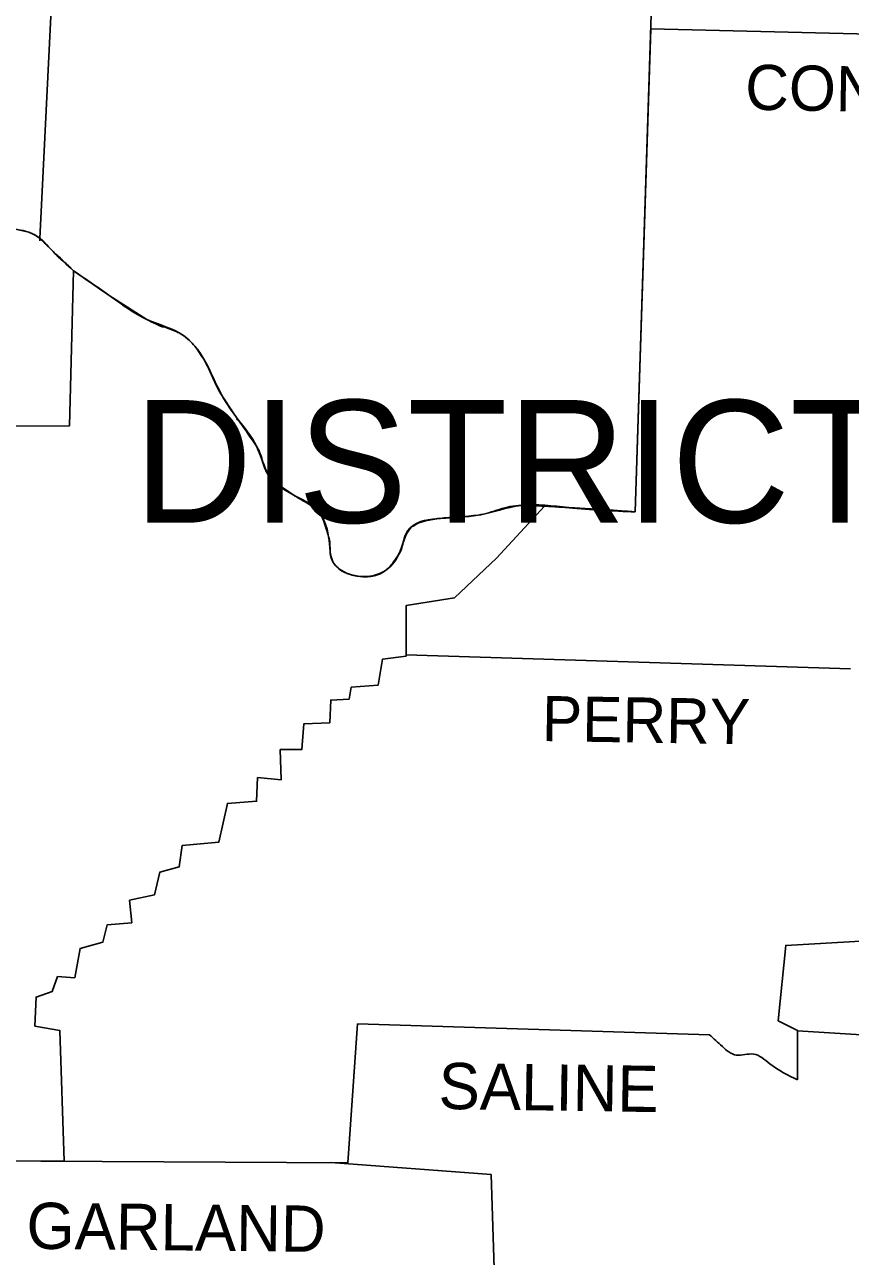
# Model space of a CAD drawing. Extents: x -13171 to 18763, y -8840 to 11152.
# Drawn here: x 12315 to 13066, y 7625 to 8746 of the extents above; entities that cross this region are included whole.
import ezdxf

# ---------------------------------------------------------------- set-up
doc = ezdxf.new("R2010")
doc.units = 0
for name, color, linetype in [('Level 1', 7, 'Continuous'), ('Level 2', 7, 'Continuous'), ('Level 3', 7, 'Continuous'), ('Level 48', 7, 'Continuous')]:
    doc.layers.add(name, color=color, linetype=linetype)

msp = doc.modelspace()

# ---------------------------------------------------------------- linework, layer by layer
at = {"layer": 'Level 1'}
msp.add_line((12329.114520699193, 8551.202475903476), (12329.114520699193, 8548.948933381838), dxfattribs=at)
for points in [[(12499.696812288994, 9145.12204334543), (12498.69559730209, 8957.894828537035), (12431.185526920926, 8956.91642185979), (12425.31508598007, 8762.213465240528), (12339.215285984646, 8759.278244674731), (12329.114520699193, 8551.202475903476)], [(12938.043358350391, 9141.567882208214), (12936.043444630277, 8881.5790968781), (12889.079917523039, 8877.665469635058), (12870.490187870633, 8302.362261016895)], [(12884.687301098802, 8741.72555171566), (13334.255019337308, 8730.904446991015), (13328.384578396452, 8489.23796307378)], [(12359.761829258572, 8521.525388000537), (12355.84820201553, 8380.634806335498), (12132.771447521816, 8379.656399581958)], [(12787.889158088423, 8307.538671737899), (12744.275708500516, 8260.290767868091), (12706.11784251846, 8224.089715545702), (12662.089535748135, 8217.240867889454), (12662.089535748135, 8171.255747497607), (12640.564585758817, 8168.320526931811), (12636.650958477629, 8144.838763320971), (12612.190788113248, 8142.881949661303), (12610.23397445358, 8132.119474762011), (12593.60105861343, 8131.141068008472), (12592.622651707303, 8110.594524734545), (12569.140888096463, 8109.616117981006), (12567.184074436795, 8086.134354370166), (12547.615938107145, 8086.134354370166), (12548.594344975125, 8058.73896343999), (12527.069394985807, 8060.695777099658), (12526.090988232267, 8039.170827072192), (12499.67400405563, 8037.214013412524), (12491.8467495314, 8001.991368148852), (12458.580917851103, 7999.056147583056), (12455.645697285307, 7979.488011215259), (12438.034374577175, 7974.595977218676), (12433.142340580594, 7954.0494339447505), (12410.638983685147, 7949.157399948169), (12412.595797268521, 7928.610856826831), (12390.092440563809, 7926.654043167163), (12386.178813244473, 7910.999534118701), (12365.632270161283, 7905.129093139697), (12360.740235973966, 7878.712108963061), (12345.085726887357, 7879.690515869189), (12340.193692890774, 7865.992820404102), (12325.517590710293, 7861.100786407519), (12324.539183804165, 7834.683802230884), (12347.042540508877, 7830.7701749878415), (12351.147833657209, 7711.716675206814)], [(13066.17155143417, 8159.514865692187), (12662.089535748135, 8172.265026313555)], [(13327.406171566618, 7976.552790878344), (13256.960880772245, 7984.380045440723), (13259.896101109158, 7957.963061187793), (13131.724808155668, 7953.07102719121), (13127.811180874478, 7914.913161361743), (13007.46714229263, 7908.064313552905), (13000.61829463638, 7839.575836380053), (13018.229617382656, 7830.7701749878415), (13018.229617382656, 7785.763461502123)], [(12938.000258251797, 7826.856547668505), (12618.061229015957, 7836.640615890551), (12609.255567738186, 7710.426136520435), (12217.892840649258, 7712.382950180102), (12215.936027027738, 7670.3114568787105)], [(13018.229617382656, 7830.219821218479), (13134.660028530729, 7822.942920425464), (13130.74640124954, 7700.642068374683), (13258.917694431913, 7695.7500342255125), (13260.874508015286, 7589.103690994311), (13321.53573062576, 7584.211657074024), (13321.53573062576, 7565.621927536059), (13378.283326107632, 7561.708300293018), (13380.240139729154, 7493.219822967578), (13509.389839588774, 7493.219822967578), (13513.303466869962, 7425.709752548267), (13632.669098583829, 7419.83931172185), (13631.689211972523, 7292.454043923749)], [(12593.638354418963, 7710.504222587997), (12739.383674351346, 7699.663661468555), (12743.297301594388, 7576.384402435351), (12726.664385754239, 7570.5139616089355), (12724.707572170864, 7504.960704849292), (12852.878865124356, 7496.155043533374), (12852.878865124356, 7442.34266857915), (12938.000258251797, 7437.45063442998), (12938.978665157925, 7383.638259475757), (12959.525208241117, 7380.703038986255), (12958.480338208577, 7303.382645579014)]]:
    msp.add_lwpolyline(points, dxfattribs=at)
for points in [[(11843.163029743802, 8639.912612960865), (11875.45045467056, 8650.67508793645), (11898.932218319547, 8652.631901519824), (11922.413981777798, 8648.718274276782), (11946.874152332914, 8638.934206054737), (11973.291136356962, 8640.891019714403), (11992.85927272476, 8647.739867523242), (12012.427409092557, 8660.459156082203), (12033.952359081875, 8664.372783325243), (12054.498902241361, 8660.459156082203), (12076.023852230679, 8654.588715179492), (12099.50561584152, 8661.43756298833), (12113.203311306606, 8674.15685154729), (12136.685074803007, 8678.070478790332), (12157.231618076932, 8678.070478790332), (12171.907720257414, 8661.43756298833), (12174.84294082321, 8643.826240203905), (12193.432670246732, 8627.193324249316), (12210.065586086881, 8616.430849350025), (12214.957620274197, 8595.884306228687), (12223.763281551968, 8581.20820385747), (12232.568943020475, 8571.424135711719), (12245.288231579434, 8565.553694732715), (12266.813181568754, 8567.510508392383), (12300.079013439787, 8560.661660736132), (12321.603963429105, 8555.769626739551), (12341.172099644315, 8539.13671078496), (12359.761829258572, 8521.525388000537)], [(12359.761829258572, 8521.525388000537), (12394.006067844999, 8498.043624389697), (12426.29349273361, 8477.497081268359), (12459.559324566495, 8462.820979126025), (12478.149054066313, 8441.296029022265), (12494.781970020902, 8408.030197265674), (12508.47966548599, 8387.483654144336), (12526.090988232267, 8362.045076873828), (12538.810276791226, 8333.671279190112), (12559.356819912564, 8318.016770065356), (12580.881769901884, 8304.31907460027), (12591.64424499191, 8279.858904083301), (12596.536279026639, 8255.398733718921), (12620.018042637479, 8243.6578519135), (12642.521399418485, 8248.54988606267), (12655.240688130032, 8263.225988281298), (12666.981569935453, 8288.664565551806), (12693.3985539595, 8296.491820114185), (12727.642792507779, 8299.427040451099), (12766.779065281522, 8308.232701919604), (12809.82896526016, 8306.275888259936), (12870.490187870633, 8302.362261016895)], [(13018.229617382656, 7785.763461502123), (12992.79104011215, 7800.439563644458), (12978.114937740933, 7809.245224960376), (12962.460428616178, 7808.2668182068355), (12949.741140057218, 7816.094072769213), (12938.000258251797, 7826.856547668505)]]:
    msp.add_spline(points, degree=3, dxfattribs=at)
at = {"layer": 'Level 48'}
for p, q in [((12884.687301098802, 8741.72555171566), (12870.490187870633, 8302.362261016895)), ((12336.985508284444, 8543.370871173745), (12335.216292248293, 8545.257728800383)), ((12338.157579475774, 8542.134739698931), (12336.985508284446, 8543.370871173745)), ((12341.172099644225, 8539.136710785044), (12338.157579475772, 8542.134739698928)), ((12350.57440254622, 8530.437965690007), (12347.724052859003, 8533.080774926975)), ((12359.761829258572, 8521.525388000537), (12394.006067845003, 8498.0436243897)), ((12394.006067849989, 8498.043624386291), (12395.274343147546, 8497.181049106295)), ((12395.274343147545, 8497.181049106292), (12426.29349273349, 8477.497081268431)), ((12426.293492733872, 8477.497081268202), (12429.384314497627, 8475.755114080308)), ((12429.384314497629, 8475.75511408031), (12434.384517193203, 8473.494056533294)), ((12442.929201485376, 8470.388573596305), (12451.472489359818, 8467.168318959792)), ((12454.447377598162, 8465.792323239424), (12455.601404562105, 8465.198804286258)), ((12459.559324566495, 8462.820979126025), (12465.077417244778, 8458.407511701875)), ((12465.077417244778, 8458.407511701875), (12470.064674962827, 8453.112212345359)), ((12470.064674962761, 8453.112212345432), (12471.857946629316, 8450.854567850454)), ((12478.149054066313, 8441.296029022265), (12481.214921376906, 8435.54579837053)), ((12481.214921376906, 8435.545798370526), (12482.446844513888, 8432.986122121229)), ((12482.446844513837, 8432.986122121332), (12486.278307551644, 8424.488532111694)), ((12486.278307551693, 8424.488532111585), (12490.203372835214, 8416.078232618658)), ((12490.203372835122, 8416.078232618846), (12493.681537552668, 8409.769684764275)), ((12505.224505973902, 8392.307514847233), (12508.47966548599, 8387.483654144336)), ((12529.512940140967, 8355.081281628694), (12531.89640473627, 8347.523716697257)), ((12538.810276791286, 8333.67127919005), (12546.329203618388, 8327.073065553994)), ((12546.329203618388, 8327.073065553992), (12548.722079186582, 8325.314940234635)), ((12548.722079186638, 8325.314940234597), (12551.453096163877, 8323.40697369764)), ((12551.45309616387, 8323.40697369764), (12559.356819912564, 8318.016770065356)), ((12559.35681991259, 8318.016770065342), (12562.013780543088, 8316.279158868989)), ((12562.01378054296, 8316.279158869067), (12563.583093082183, 8315.347649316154)), ((12564.745625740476, 8314.688091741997), (12566.806447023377, 8313.558564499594)), ((12570.303433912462, 8311.667015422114), (12578.385930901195, 8306.493392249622)), ((12747.139288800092, 8304.609341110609), (12756.884493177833, 8307.196396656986)), ((12756.884493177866, 8307.196396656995), (12766.779065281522, 8308.232701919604)), ((12809.82896526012, 8306.275888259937), (12787.889158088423, 8307.538671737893)), ((12587.724266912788, 8292.793198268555), (12589.701947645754, 8286.305888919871)), ((12673.590973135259, 8292.34473853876), (12679.810251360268, 8294.357804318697)), ((12679.810251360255, 8294.357804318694), (12688.070499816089, 8295.834292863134)), ((12701.973495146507, 8297.302935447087), (12710.569627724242, 8297.863531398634)), ((12737.429904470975, 8301.632550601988), (12738.178153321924, 8301.848966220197)), ((12659.997705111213, 8276.608187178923), (12662.40581236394, 8283.264485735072)), ((12665.54631513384, 8287.482889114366), (12666.981569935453, 8288.664565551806)), ((12592.388054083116, 8276.876146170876), (12592.727311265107, 8273.839962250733)), ((12592.727311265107, 8273.839962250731), (12592.728502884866, 8273.821632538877)), ((12592.728502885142, 8273.821632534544), (12592.732107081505, 8273.765436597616)), ((12592.732107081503, 8273.765436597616), (12592.930437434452, 8267.598127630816)), ((12656.925960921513, 8266.29124960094), (12658.146309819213, 8269.620433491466)), ((12593.71228427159, 8261.38996835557), (12594.777623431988, 8258.354636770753)), ((12650.430288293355, 8256.425434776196), (12655.240688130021, 8263.225988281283)), ((12596.536279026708, 8255.39873371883), (12601.599807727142, 8250.269510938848)), ((12601.599807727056, 8250.269510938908), (12607.436031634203, 8246.863120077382)), ((12646.433002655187, 8251.876134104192), (12648.801596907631, 8254.419431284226)), ((12648.801596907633, 8254.419431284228), (12649.674224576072, 8255.468539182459)), ((12611.542209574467, 8245.368517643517), (12613.692820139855, 8244.789315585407)), ((12616.861512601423, 8244.13259844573), (12617.179931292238, 8244.076336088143)), ((12617.179931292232, 8244.076336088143), (12620.018042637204, 8243.657851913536)), ((12620.018042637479, 8243.6578519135), (12625.64960856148, 8243.326480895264)), ((12625.649608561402, 8243.32648089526), (12628.769364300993, 8243.498476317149)), ((12628.769364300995, 8243.498476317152), (12631.435420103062, 8243.875166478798)), ((12631.435420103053, 8243.875166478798), (12637.13838210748, 8245.538203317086)), ((12662.089535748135, 8172.265026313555), (13066.17155143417, 8159.514865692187))]:
    msp.add_line(p, q, dxfattribs=at)
for points in [[(12499.696812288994, 9145.12204334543), (12498.69559730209, 8957.894828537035), (12431.185526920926, 8956.91642185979), (12425.31508598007, 8762.213465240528), (12339.215285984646, 8759.278244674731), (12329.114520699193, 8551.202475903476)], [(12870.490187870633, 8302.362261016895), (12889.079917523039, 8877.665469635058), (12936.043444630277, 8881.5790968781), (12938.043358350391, 9141.567882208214)], [(13328.384578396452, 8489.23796307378), (13331.259748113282, 8607.599115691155), (13334.255019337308, 8730.904446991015), (12884.687301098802, 8741.72555171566)], [(12359.761829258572, 8521.525388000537), (12355.84820201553, 8380.634806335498), (12132.771447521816, 8379.656399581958), (12103.419243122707, 8354.21782231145), (12086.786327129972, 8315.081549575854), (12062.326156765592, 8317.038363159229), (12061.347749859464, 8294.535006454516), (12032.973952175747, 8291.59978588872), (12033.952359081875, 8271.053242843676), (11892.083370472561, 8274.966870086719), (11887.191336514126, 8259.312360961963), (11828.486927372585, 8257.35554737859), (11827.900316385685, 8085.771835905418)], [(12103.419243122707, 8354.21782231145), (12132.771447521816, 8379.656399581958), (12355.84820201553, 8380.634806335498), (12359.761829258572, 8521.525388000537)], [(12351.147833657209, 7711.716675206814), (12347.042540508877, 7830.7701749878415), (12324.539183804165, 7834.683802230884), (12325.517590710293, 7861.100786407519), (12340.193692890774, 7865.992820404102), (12345.085726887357, 7879.690515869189), (12360.740235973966, 7878.712108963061), (12365.632270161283, 7905.129093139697), (12386.178813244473, 7910.999534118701), (12390.092440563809, 7926.654043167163), (12412.595797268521, 7928.610856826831), (12410.638983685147, 7949.157399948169), (12433.142340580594, 7954.0494339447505), (12438.034374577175, 7974.595977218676), (12455.645697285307, 7979.488011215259), (12458.580917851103, 7999.056147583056), (12491.8467495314, 8001.991368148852), (12499.67400405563, 8037.214013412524), (12526.090988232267, 8039.170827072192), (12527.069394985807, 8060.695777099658), (12548.594344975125, 8058.73896343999), (12547.615938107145, 8086.134354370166), (12567.184074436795, 8086.134354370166), (12569.140888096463, 8109.616117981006), (12592.622651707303, 8110.594524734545), (12593.60105861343, 8131.141068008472), (12610.23397445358, 8132.119474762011), (12612.190788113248, 8142.881949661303), (12636.650958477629, 8144.838763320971), (12640.564585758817, 8168.320526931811), (12662.089535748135, 8171.255747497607), (12662.089535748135, 8172.234154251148), (12662.089535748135, 8217.240867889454), (12706.11784251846, 8224.089715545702), (12744.275708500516, 8260.290767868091), (12787.889158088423, 8307.538671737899)], [(12787.889158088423, 8307.538671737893), (12744.275708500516, 8260.290767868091), (12706.11784251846, 8224.089715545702), (12662.089535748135, 8217.240867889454), (12662.089535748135, 8172.265026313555)], [(12215.936027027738, 7670.3114568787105), (12217.892840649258, 7712.382950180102), (12351.147833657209, 7711.716675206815)]]:
    msp.add_lwpolyline(points, dxfattribs=at)
for points in [[(12329.114490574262, 8551.20243986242), (12321.603963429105, 8555.769626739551), (12310.91566817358, 8558.639119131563), (12300.079013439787, 8560.661660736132), (12266.813181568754, 8567.510508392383), (12261.473826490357, 8567.631179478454), (12256.077744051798, 8566.639145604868), (12250.668142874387, 8565.593589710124), (12245.288231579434, 8565.553694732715), (12232.568943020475, 8571.424135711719), (12223.763281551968, 8581.20820385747), (12219.058710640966, 8588.43034832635), (12216.953924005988, 8592.132956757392), (12214.957620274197, 8595.884306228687), (12213.516036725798, 8600.955689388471), (12213.119763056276, 8606.464574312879), (12212.419409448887, 8611.819960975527), (12210.065586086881, 8616.430849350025), (12208.261658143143, 8618.178220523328), (12206.286113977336, 8619.674661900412), (12202.006159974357, 8622.186865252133), (12197.597690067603, 8624.511679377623), (12193.432670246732, 8627.193324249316), (12174.84294082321, 8643.826240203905), (12173.146282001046, 8647.761102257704), (12172.986926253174, 8652.32111227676), (12173.021772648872, 8657.036516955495), (12171.907720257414, 8661.43756298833), (12169.152112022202, 8666.573161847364), (12165.990428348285, 8671.440553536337), (12162.11836508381, 8675.464678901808), (12157.231618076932, 8678.070478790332), (12154.678837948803, 8678.70238865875), (12152.113533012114, 8679.052592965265), (12146.961519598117, 8679.110204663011), (12136.685074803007, 8678.070478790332), (12113.203311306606, 8674.15685154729), (12109.345341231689, 8671.767770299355), (12106.316483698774, 8668.196166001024), (12103.306616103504, 8664.425082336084), (12099.50561584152, 8661.43756298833), (12093.654654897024, 8658.495649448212), (12087.79106270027, 8655.989609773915), (12081.914306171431, 8654.49533475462), (12076.023852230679, 8654.588715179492), (12070.657596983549, 8655.831982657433), (12065.299422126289, 8657.408942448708), (12059.922224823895, 8659.04339883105), (12054.498902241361, 8660.459156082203), (12033.952359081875, 8664.372783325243), (12023.187925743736, 8663.875894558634), (12017.803641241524, 8662.458353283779), (12012.427409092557, 8660.459156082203), (12007.149267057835, 8657.585419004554), (12002.450083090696, 8654.126112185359), (11997.84752803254, 8650.653505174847), (11992.85927272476, 8647.739867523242), (11983.23233915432, 8643.870108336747), (11973.291136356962, 8640.891019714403), (11960.043200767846, 8638.52371095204), (11946.874152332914, 8638.934206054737), (11940.688849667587, 8640.807815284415), (11934.692412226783, 8643.609529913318), (11928.671802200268, 8646.51959966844), (11922.413981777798, 8648.718274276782), (11910.711803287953, 8651.241368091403), (11898.932218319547, 8652.631901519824), (11887.186873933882, 8652.456639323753), (11875.45045467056, 8650.67508793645), (11867.131084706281, 8648.600591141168), (11859.001968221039, 8646.157567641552), (11843.163029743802, 8639.912612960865)], [(12329.114490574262, 8551.20243986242), (12335.216292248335, 8545.257728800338), (12338.157579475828, 8542.134739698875), (12341.172099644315, 8539.13671078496), (12350.574402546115, 8530.437965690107), (12359.761829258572, 8521.525388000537)], [(12335.216292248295, 8545.257728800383), (12333.736371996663, 8546.79219506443), (12332.24207069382, 8548.313119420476), (12330.709429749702, 8549.79252623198), (12329.114490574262, 8551.20243986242)], [(12347.724052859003, 8533.080774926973), (12341.172099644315, 8539.13671078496), (12341.172099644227, 8539.136710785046)], [(12359.761829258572, 8521.525388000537), (12357.496474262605, 8523.787717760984), (12355.207142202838, 8526.02339302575), (12352.89829699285, 8528.238210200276), (12350.57440254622, 8530.437965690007)], [(12787.889158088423, 8307.538671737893), (12766.779065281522, 8308.232701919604), (12756.884493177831, 8307.196396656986), (12747.139288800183, 8304.609341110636), (12737.42990446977, 8301.632550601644), (12727.642792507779, 8299.427040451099), (12719.141283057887, 8298.472076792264), (12710.569627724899, 8297.863531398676), (12701.97349514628, 8297.30293544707), (12693.3985539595, 8296.491820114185), (12679.810251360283, 8294.3578043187), (12666.981569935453, 8288.664565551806), (12665.54631513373, 8287.48288911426), (12664.322051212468, 8286.179350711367), (12662.405812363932, 8283.264485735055), (12659.99770511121, 8276.60818717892), (12658.146309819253, 8269.6204334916), (12656.925960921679, 8266.29124960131), (12655.240688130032, 8263.225988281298), (12649.674224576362, 8255.468539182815), (12646.433002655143, 8251.876134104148), (12642.521399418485, 8248.54988606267), (12637.138382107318, 8245.538203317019), (12631.43542010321, 8243.875166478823), (12625.64960856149, 8243.326480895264), (12620.018042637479, 8243.6578519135), (12613.69282014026, 8244.78931558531), (12607.436031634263, 8246.863120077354), (12601.599807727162, 8250.26951093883), (12596.536279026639, 8255.398733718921), (12595.558862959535, 8256.865181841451), (12594.77762343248, 8258.354636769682), (12593.712284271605, 8261.389968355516), (12592.93043743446, 8267.598127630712), (12592.728502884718, 8273.821632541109), (12592.388054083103, 8276.876146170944), (12591.64424499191, 8279.858904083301), (12589.701947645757, 8286.30588891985), (12587.724266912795, 8292.793198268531), (12585.015956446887, 8298.92840315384), (12580.881769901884, 8304.31907460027), (12579.651004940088, 8305.444500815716), (12578.385930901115, 8306.493392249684), (12570.3034339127, 8311.667015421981), (12564.745625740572, 8314.688091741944), (12562.013780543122, 8316.279158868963), (12559.356819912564, 8318.016770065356), (12548.72207918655, 8325.314940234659), (12538.810276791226, 8333.671279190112), (12536.402315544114, 8336.73873941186), (12534.556983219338, 8340.133382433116), (12531.896404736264, 8347.523716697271), (12529.512940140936, 8355.081281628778), (12526.090988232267, 8362.045076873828), (12508.47966548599, 8387.483654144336), (12494.781970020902, 8408.030197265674), (12490.203372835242, 8416.078232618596), (12486.278307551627, 8424.48853211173), (12482.446844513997, 8432.986122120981), (12478.149054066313, 8441.296029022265), (12470.064674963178, 8453.112212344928), (12459.559324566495, 8462.820979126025), (12455.601404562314, 8465.198804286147), (12451.472489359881, 8467.168318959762), (12442.929201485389, 8470.388573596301), (12434.384517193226, 8473.494056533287), (12426.29349273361, 8477.497081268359), (12394.006067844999, 8498.043624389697), (12359.761829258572, 8521.525388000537)], [(12434.384517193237, 8473.494056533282), (12442.929201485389, 8470.388573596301), (12442.929201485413, 8470.388573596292)], [(12451.472489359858, 8467.16831895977), (12451.472489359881, 8467.168318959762), (12454.447377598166, 8465.792323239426)], [(12455.601404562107, 8465.198804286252), (12455.601404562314, 8465.198804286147), (12459.559324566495, 8462.820979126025), (12459.559324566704, 8462.820979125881)], [(12471.85794662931, 8450.854567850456), (12478.149054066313, 8441.296029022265), (12478.149054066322, 8441.296029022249)], [(12493.681537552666, 8409.76968476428), (12494.781970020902, 8408.030197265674), (12494.781970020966, 8408.030197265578)], [(12508.479665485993, 8387.483654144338), (12508.47966548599, 8387.483654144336), (12510.662307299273, 8384.281218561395)], [(12510.662307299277, 8384.281218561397), (12526.090988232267, 8362.045076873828), (12526.090988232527, 8362.045076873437)], [(12526.090988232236, 8362.045076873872), (12526.090988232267, 8362.045076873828), (12528.073612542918, 8358.560405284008)], [(12528.07361254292, 8358.560405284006), (12529.512940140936, 8355.081281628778), (12529.51294014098, 8355.081281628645)], [(12531.896404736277, 8347.523716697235), (12534.556983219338, 8340.133382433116), (12534.556983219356, 8340.133382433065)], [(12563.58309308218, 8315.347649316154), (12564.745625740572, 8314.688091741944), (12564.74562574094, 8314.688091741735)], [(12566.80644702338, 8313.558564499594), (12570.3034339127, 8311.667015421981), (12570.303433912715, 8311.667015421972)], [(12738.178153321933, 8301.8489662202), (12747.139288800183, 8304.609341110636), (12747.13928880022, 8304.609341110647)], [(12666.98156993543, 8288.664565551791), (12666.981569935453, 8288.664565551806), (12673.590973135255, 8292.344738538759)], [(12688.07049981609, 8295.834292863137), (12693.3985539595, 8296.491820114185), (12693.398553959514, 8296.491820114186)], [(12693.398553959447, 8296.491820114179), (12693.3985539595, 8296.491820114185), (12699.919480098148, 8297.142991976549)], [(12699.91948009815, 8297.142991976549), (12701.97349514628, 8297.30293544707), (12701.973495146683, 8297.302935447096)], [(12710.569627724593, 8297.863531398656), (12710.569627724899, 8297.863531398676), (12719.141283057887, 8298.472076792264), (12719.141283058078, 8298.472076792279)], [(12719.141283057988, 8298.472076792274), (12727.642792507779, 8299.427040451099), (12727.642792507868, 8299.427040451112)], [(12727.642792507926, 8299.42704045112), (12737.42990446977, 8301.632550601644), (12737.429904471, 8301.632550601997)], [(12589.701947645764, 8286.30588891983), (12591.64424499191, 8279.858904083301), (12591.644244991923, 8279.858904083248)], [(12591.644244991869, 8279.858904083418), (12591.64424499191, 8279.858904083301), (12592.388054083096, 8276.876146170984)], [(12658.146309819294, 8269.620433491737), (12659.99770511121, 8276.60818717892), (12659.997705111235, 8276.608187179)], [(12592.930437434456, 8267.5981276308), (12592.93043743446, 8267.598127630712), (12593.712284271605, 8261.389968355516), (12593.71228427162, 8261.389968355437)], [(12594.777623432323, 8258.354636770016), (12594.77762343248, 8258.354636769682), (12595.55886295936, 8256.865181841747)], [(12655.240688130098, 8263.2259882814), (12656.925960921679, 8266.29124960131), (12656.925960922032, 8266.291249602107)], [(12595.558862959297, 8256.865181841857), (12596.536279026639, 8255.398733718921), (12596.536279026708, 8255.39873371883)], [(12607.436031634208, 8246.86312007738), (12607.436031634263, 8246.863120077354), (12611.542209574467, 8245.368517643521)], [(12637.138382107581, 8245.538203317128), (12642.521399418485, 8248.54988606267), (12642.521399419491, 8248.549886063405)], [(12642.521399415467, 8248.549886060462), (12642.521399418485, 8248.54988606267), (12646.43300265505, 8251.876134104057)], [(12649.674224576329, 8255.468539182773), (12649.674224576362, 8255.468539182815), (12650.430288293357, 8256.425434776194)], [(12613.692820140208, 8244.789315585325), (12613.69282014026, 8244.78931558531), (12616.861512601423, 8244.13259844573)]]:
    msp.add_spline(points, degree=3, dxfattribs=at)
for points, degree in [([(12494.781970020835, 8408.030197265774), (12494.781970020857, 8408.03019726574), (12494.78197002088, 8408.030197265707), (12494.781970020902, 8408.030197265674), (12498.227469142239, 8402.769088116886), (12501.712844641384, 8397.528719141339), (12505.224505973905, 8392.307514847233)], 3), ([(12534.556983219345, 8340.133382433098), (12535.636206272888, 8337.782365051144), (12536.980881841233, 8335.586052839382), (12538.810276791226, 8333.671279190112), (12538.810276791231, 8333.671279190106), (12538.810276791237, 8333.6712791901), (12538.810276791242, 8333.671279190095)], 3), ([(12578.385930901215, 8306.493392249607), (12578.82614071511, 8306.164001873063), (12579.235569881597, 8305.803245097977), (12579.651004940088, 8305.444500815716), (12580.072607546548, 8305.080430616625), (12580.48119763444, 8304.70949433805), (12580.881769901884, 8304.31907460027), (12580.88176990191, 8304.319074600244), (12580.881769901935, 8304.31907460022), (12580.881769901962, 8304.319074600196)], 3), ([(12580.881769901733, 8304.319074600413), (12580.881769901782, 8304.319074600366), (12580.881769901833, 8304.319074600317), (12580.881769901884, 8304.31907460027), (12582.574727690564, 8302.689876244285), (12583.914165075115, 8300.87118415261), (12585.015956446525, 8298.928403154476)], 3), ([(12766.779065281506, 8308.232701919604), (12766.779065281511, 8308.232701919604), (12766.779065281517, 8308.232701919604), (12766.779065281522, 8308.232701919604), (12781.112959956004, 8308.052115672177), (12795.491773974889, 8307.16036329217), (12809.82896526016, 8306.275888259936), (12830.052490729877, 8305.02827964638), (12850.282324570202, 8303.951215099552), (12870.490187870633, 8302.362261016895)], 3), ([(12870.490187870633, 8302.362261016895), (12850.282324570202, 8303.951215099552), (12830.052490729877, 8305.02827964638), (12809.82896526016, 8306.275888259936)], 2), ([(12585.015956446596, 8298.928403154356), (12585.015956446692, 8298.928403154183), (12585.01595644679, 8298.928403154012), (12585.015956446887, 8298.92840315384), (12586.131266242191, 8296.953856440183), (12587.068606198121, 8294.930780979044), (12587.724266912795, 8292.793198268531), (12587.724266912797, 8292.793198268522), (12587.724266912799, 8292.793198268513), (12587.7242669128, 8292.793198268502)], 3), ([(12662.40581236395, 8283.264485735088), (12662.894606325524, 8284.33382120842), (12663.57238524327, 8285.273333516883), (12664.322051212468, 8286.179350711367), (12664.322051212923, 8286.179350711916), (12664.322051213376, 8286.179350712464), (12664.32205121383, 8286.179350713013)], 3), ([(12664.322051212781, 8286.179350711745), (12664.697770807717, 8286.632568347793), (12665.104460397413, 8287.067883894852), (12665.546315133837, 8287.482889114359)], 2)]:
    msp.add_open_spline(points, degree=degree, dxfattribs=at)

# ---------------------------------------------------------------- texts
at = {"layer": 'Level 2'}
for s, height, rotation, p in [('CONWAY', 41.081345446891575, 359.0371361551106, (12970.287683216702, 8668.28641064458)), ('PERRY', 41.09308632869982, 359.08578335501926, (12785.368794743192, 8093.961608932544)), ('SALINE', 42.07344995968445, 359.1491361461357, (12691.44174033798, 7759.346477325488)), ('GARLAND', 42.07344995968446, 359.3657555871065, (12316.711929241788, 7632.153591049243))]:
    msp.add_text(s, height=height, rotation=rotation, dxfattribs=at).set_placement(p)
at = {"layer": 'Level 3'}
msp.add_text('DISTRICT', height=111.53837717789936, dxfattribs=at).set_placement((12414.55261092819, 8292.578192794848))

doc.saveas('drawing.dxf')
